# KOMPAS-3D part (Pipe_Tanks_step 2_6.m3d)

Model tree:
1. X Axis
2. Y Axis
3. Z Axis  (labels: T-Bend Dn 50; Pipe Dn 50)
     Òîëùèíà ñòåíêè 1 = 1

Referenced files in C:\Documents and Settings\kashirsky\Мои документы\Camtasia Studio\Pipelines3D\Tanks\: Tanks_step 2.a3d
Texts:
  Pipe Dn 50
  Steel ASTM A295
  Three Point Plane
  Plane at Angle
  Line and Point Plane
  Axis through Two Vertices
  Axis of Feature
  Axis of Conical Surface
  Axis through Edge
  Trim by Surface
  Trim by Sketch
  Feature with No History
  Intersection Axis of Two Planes
  Two Line Plane
  Line and Face Plane
  Bend by line
  Hole in sheet body
  Cut in sheet body
  Point in CM
  Linear Dimension from Line to Point
  Surface Finish Symbol
  Geometric Tolerance Symbol
  Leader #1
  Leader #2
  Leader #3
  Shape Deviations and Datum
  Node point number
  Mark of coordination axis
  Node point designation
  Mark/Reference designation with leader
  Mark/reference designation on line
  Mark/Reference designation without leader
  T-Bend Dn 50
  Plane of section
